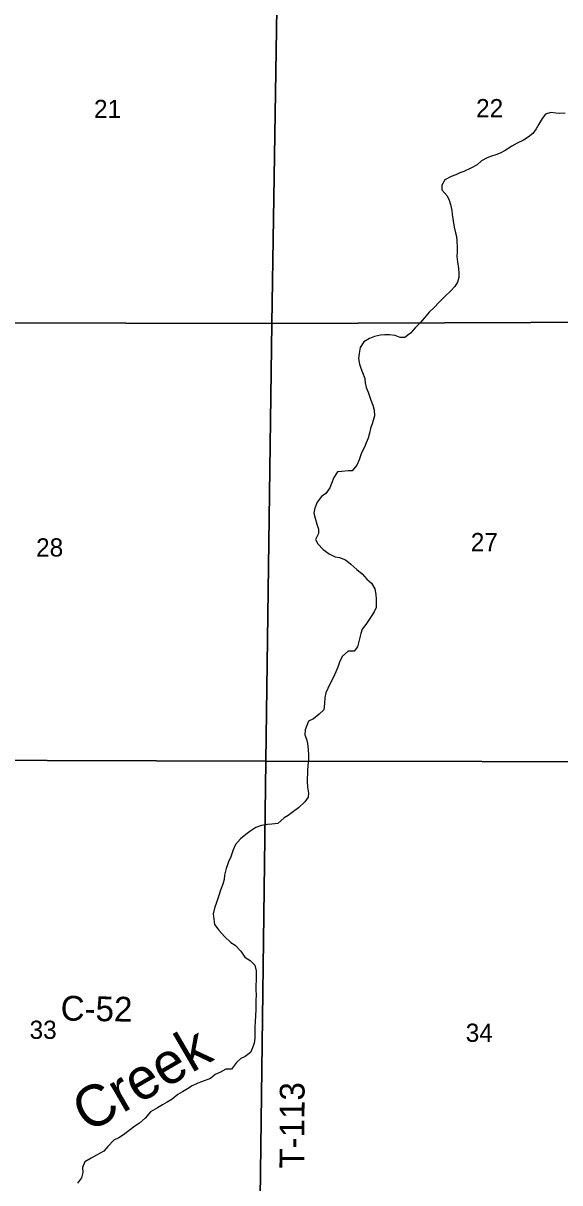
# Model space of a CAD drawing. Extents: x 1772825 to 1773716, y 1138558 to 1139032.
# Drawn here: x 1772826.206 to 1772826.822, y 1138561.147 to 1138562.479 of the extents above; entities that cross this region are included whole.
import ezdxf

# ---------------------------------------------------------------- set-up
doc = ezdxf.new("R2010")
doc.units = 0
for name, color, linetype in [('GM_X_County_Road_Text', 7, 'Continuous'), ('GM_X_Minor_River', 7, 'Continuous'), ('GM_X_Minor_River_Text', 7, 'Continuous'), ('GM_X_Section', 7, 'Continuous'), ('GM_X_Section_Text', 7, 'Continuous'), ('GM_X_Township_Road_Text', 7, 'Continuous')]:
    doc.layers.add(name, color=color, linetype=linetype)

msp = doc.modelspace()

# ---------------------------------------------------------------- linework, layer by layer
at = {"layer": 'GM_X_Minor_River'}
for points in [[(1772826.8285, 1138562.3755), (1772826.8224, 1138562.375), (1772826.8177, 1138562.3752), (1772826.8122, 1138562.3762), (1772826.8059, 1138562.3742), (1772826.8021, 1138562.3691), (1772826.7982, 1138562.3627), (1772826.7951, 1138562.3572), (1772826.7913, 1138562.3519), (1772826.7862, 1138562.3478), (1772826.7806, 1138562.3444), (1772826.7734, 1138562.3408), (1772826.7675, 1138562.3375), (1772826.7595, 1138562.3324), (1772826.7538, 1138562.3294), (1772826.7488, 1138562.3274), (1772826.7441, 1138562.3259), (1772826.7391, 1138562.3242), (1772826.7325, 1138562.3205), (1772826.7277, 1138562.3159), (1772826.7202, 1138562.312), (1772826.7124, 1138562.3085), (1772826.7077, 1138562.3068), (1772826.7029, 1138562.3044), (1772826.6978, 1138562.3027), (1772826.6904, 1138562.2988), (1772826.6869, 1138562.2927), (1772826.6871, 1138562.2874), (1772826.6929, 1138562.2805), (1772826.6953, 1138562.2754), (1772826.6968, 1138562.2704), (1772826.6983, 1138562.2636), (1772826.6988, 1138562.2588), (1772826.6999, 1138562.2518), (1772826.7012, 1138562.2444), (1772826.7021, 1138562.2395), (1772826.7037, 1138562.2338), (1772826.7041, 1138562.2288), (1772826.7044, 1138562.2212), (1772826.7044, 1138562.2161), (1772826.7041, 1138562.2108), (1772826.7049, 1138562.2045), (1772826.7059, 1138562.1969), (1772826.7063, 1138562.1916), (1772826.7066, 1138562.1867), (1772826.7049, 1138562.1814), (1772826.7018, 1138562.1763), (1772826.697, 1138562.171), (1772826.6913, 1138562.1657), (1772826.684, 1138562.1582), (1772826.6787, 1138562.1527), (1772826.6724, 1138562.1469), (1772826.6668, 1138562.1401), (1772826.6615, 1138562.1343), (1772826.6563, 1138562.1288), (1772826.6511, 1138562.1226), (1772826.6445, 1138562.1177), (1772826.6392, 1138562.1179), (1772826.6335, 1138562.1199), (1772826.6268, 1138562.1209), (1772826.6215, 1138562.1209), (1772826.6166, 1138562.1204), (1772826.6098, 1138562.1187), (1772826.6037, 1138562.1167), (1772826.5974, 1138562.1129), (1772826.5932, 1138562.1061), (1772826.592, 1138562.0993), (1772826.5914, 1138562.0936), (1772826.5924, 1138562.0872), (1772826.5939, 1138562.0824), (1772826.596, 1138562.0776), (1772826.5984, 1138562.0706), (1772826.5989, 1138562.0655), (1772826.6002, 1138562.0604), (1772826.6023, 1138562.055), (1772826.6056, 1138562.0459), (1772826.6077, 1138562.0402), (1772826.6091, 1138562.0341), (1772826.6095, 1138562.0276), (1772826.6073, 1138562.0197), (1772826.6052, 1138562.0133), (1772826.604, 1138562.008), (1772826.6023, 1138562.0021), (1772826.6001, 1138561.9966), (1772826.5982, 1138561.9917), (1772826.5947, 1138561.9853), (1772826.5922, 1138561.9773), (1772826.5895, 1138561.9713), (1772826.584, 1138561.9647), (1772826.5792, 1138561.9645), (1772826.572, 1138561.9638), (1772826.5673, 1138561.9633), (1772826.5629, 1138561.957), (1772826.5602, 1138561.9502), (1772826.5584, 1138561.9451)], [(1772826.5584, 1138561.9451), (1772826.5536, 1138561.9387), (1772826.5489, 1138561.9351), (1772826.5439, 1138561.9287), (1772826.541, 1138561.9219), (1772826.54, 1138561.916), (1772826.5413, 1138561.9101), (1772826.5433, 1138561.9035), (1772826.5455, 1138561.8976), (1772826.5453, 1138561.8925), (1772826.542, 1138561.8857), (1772826.5447, 1138561.8809), (1772826.5507, 1138561.8744), (1772826.5575, 1138561.8694), (1772826.5643, 1138561.8659), (1772826.5694, 1138561.8651), (1772826.5762, 1138561.8624), (1772826.5826, 1138561.8573), (1772826.5894, 1138561.8513), (1772826.5955, 1138561.8465), (1772826.6009, 1138561.8404), (1772826.606, 1138561.8355), (1772826.6101, 1138561.8292), (1772826.6112, 1138561.8227), (1772826.6116, 1138561.8174), (1772826.6115, 1138561.8077), (1772826.6092, 1138561.8026), (1772826.6044, 1138561.7951), (1772826.5998, 1138561.7883), (1772826.5954, 1138561.7828), (1772826.5938, 1138561.7779), (1772826.5915, 1138561.7688), (1772826.5901, 1138561.7627), (1772826.5861, 1138561.7576), (1772826.5794, 1138561.7575), (1772826.573, 1138561.7518), (1772826.5697, 1138561.7462), (1772826.5674, 1138561.739), (1772826.5652, 1138561.7339), (1772826.5623, 1138561.7271), (1772826.5585, 1138561.7197), (1772826.556, 1138561.7146), (1772826.5539, 1138561.7095), (1772826.5525, 1138561.7042), (1772826.5521, 1138561.6974), (1772826.5516, 1138561.6903), (1772826.5459, 1138561.6851), (1772826.5396, 1138561.6798), (1772826.5339, 1138561.6772), (1772826.5318, 1138561.6723), (1772826.53, 1138561.6673), (1772826.5296, 1138561.6615), (1772826.5315, 1138561.6565), (1772826.5326, 1138561.6514), (1772826.5335, 1138561.6447), (1772826.534, 1138561.6381), (1772826.534, 1138561.6328), (1772826.533, 1138561.6267), (1772826.5325, 1138561.6203), (1772826.5324, 1138561.6078), (1772826.5326, 1138561.6013), (1772826.5337, 1138561.5946), (1772826.5335, 1138561.5899), (1772826.5298, 1138561.5846), (1772826.5224, 1138561.5778), (1772826.5166, 1138561.5733), (1772826.5105, 1138561.5688), (1772826.5058, 1138561.566), (1772826.4985, 1138561.5596), (1772826.4917, 1138561.5587), (1772826.4869, 1138561.5586), (1772826.4797, 1138561.5573), (1772826.4732, 1138561.5551), (1772826.4666, 1138561.5504), (1772826.4618, 1138561.547), (1772826.4559, 1138561.5419), (1772826.4501, 1138561.5355), (1772826.4473, 1138561.5295), (1772826.4445, 1138561.5215), (1772826.442, 1138561.5156), (1772826.4393, 1138561.5081), (1772826.4374, 1138561.5003), (1772826.4368, 1138561.4952), (1772826.4356, 1138561.4901), (1772826.4329, 1138561.4829), (1772826.4304, 1138561.4757), (1772826.428, 1138561.4691), (1772826.4259, 1138561.4626), (1772826.4245, 1138561.4558), (1772826.4251, 1138561.4499), (1772826.426, 1138561.4437), (1772826.431, 1138561.437), (1772826.4374, 1138561.4297), (1772826.4446, 1138561.423), (1772826.4497, 1138561.4198), (1772826.4561, 1138561.4129), (1772826.4606, 1138561.4062), (1772826.467, 1138561.4022), (1772826.4723, 1138561.3968), (1772826.4738, 1138561.3904), (1772826.4737, 1138561.3796)], [(1772826.4737, 1138561.3796), (1772826.4735, 1138561.3737), (1772826.4734, 1138561.3682), (1772826.4736, 1138561.363), (1772826.4733, 1138561.3562), (1772826.4732, 1138561.3452), (1772826.4728, 1138561.3397), (1772826.4724, 1138561.3316), (1772826.4722, 1138561.3262), (1772826.4723, 1138561.3196), (1772826.4723, 1138561.3133), (1772826.4713, 1138561.3073), (1772826.4697, 1138561.3022), (1772826.4674, 1138561.2965), (1772826.4611, 1138561.2922), (1772826.4561, 1138561.2897), (1772826.4512, 1138561.2852), (1772826.4454, 1138561.2777), (1772826.439, 1138561.2774), (1772826.4329, 1138561.274), (1772826.4266, 1138561.2714), (1772826.4213, 1138561.2669), (1772826.411, 1138561.2631)], [(1772826.411, 1138561.2631), (1772826.4067, 1138561.2616), (1772826.4004, 1138561.2585), (1772826.3947, 1138561.2548), (1772826.3893, 1138561.2515), (1772826.3836, 1138561.2483), (1772826.3772, 1138561.243), (1772826.3715, 1138561.2398), (1772826.3662, 1138561.2365), (1772826.3603, 1138561.2331), (1772826.3524, 1138561.2286), (1772826.3461, 1138561.2214), (1772826.3397, 1138561.2157), (1772826.3342, 1138561.2121), (1772826.328, 1138561.207), (1772826.3212, 1138561.202), (1772826.3159, 1138561.1988), (1772826.3104, 1138561.196), (1772826.3032, 1138561.1889), (1772826.2987, 1138561.1834), (1772826.2905, 1138561.1789), (1772826.2843, 1138561.1755), (1772826.2769, 1138561.1711), (1772826.2741, 1138561.1648), (1772826.2745, 1138561.1588), (1772826.273, 1138561.1527), (1772826.2686, 1138561.1465)]]:
    msp.add_lwpolyline(points, dxfattribs=at)
at = {"layer": 'GM_X_Section'}
for points in [[(1772825.9968, 1138562.6348), (1772826.4997, 1138562.64), (1772826.4919, 1138562.1338), (1772825.9889, 1138562.1349)], [(1772826.4997, 1138562.64), (1772826.9906, 1138562.6389), (1772826.9874, 1138562.1357), (1772826.4919, 1138562.1338)], [(1772825.9889, 1138562.1349), (1772826.4919, 1138562.1338), (1772826.4849, 1138561.6314), (1772825.9823, 1138561.6329)], [(1772826.9874, 1138562.1357), (1772826.9813, 1138561.6303), (1772826.4849, 1138561.6314), (1772826.4919, 1138562.1338)], [(1772825.9823, 1138561.6329), (1772826.4849, 1138561.6314), (1772826.4783, 1138561.1299), (1772825.9788, 1138561.1333)], [(1772826.4849, 1138561.6314), (1772826.9813, 1138561.6303), (1772826.9799, 1138561.1276), (1772826.9762, 1138561.1277), (1772826.4923, 1138561.13), (1772826.4783, 1138561.1299)]]:
    msp.add_lwpolyline(points, close=True, dxfattribs=at)

# ---------------------------------------------------------------- texts
at = {"layer": 'GM_X_County_Road_Text'}
msp.add_text('C-52', height=0.02841, rotation=358.9772, dxfattribs=at).set_placement((1772826.249, 1138561.3335))
at = {"layer": 'GM_X_Minor_River_Text'}
msp.add_text('Creek', height=0.04737, rotation=30.2292, dxfattribs=at).set_placement((1772826.2807, 1138561.2036))
at = {"layer": 'GM_X_Section_Text'}
for s, p in [('21', (1772826.2875, 1138562.3697)), ('22', (1772826.7263, 1138562.3706)), ('27', (1772826.7202, 1138561.8723)), ('28', (1772826.221, 1138561.8662)), ('33', (1772826.2135, 1138561.3123)), ('34', (1772826.7144, 1138561.3089))]:
    msp.add_text(s, height=0.02093, rotation=0, dxfattribs=at).set_placement(p)
at = {"layer": 'GM_X_Township_Road_Text'}
msp.add_text('T-113', height=0.02841, rotation=89.7247, dxfattribs=at).set_placement((1772826.5289, 1138561.1633))

doc.saveas('drawing.dxf')
